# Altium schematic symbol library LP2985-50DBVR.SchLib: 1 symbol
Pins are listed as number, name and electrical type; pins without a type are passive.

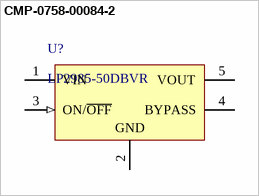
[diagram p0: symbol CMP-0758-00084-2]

## CMP-0758-00084-2
designator U?, comment LP2985-50DBVR
Single Output Low Noise LDO, 150 mA, Fixed 5 V Output, 1.5% Tolerance, 2.2 to 16 V Input, Low IQ, 5-Pin SOT-23 (DBV), -40 to 125 degC, Green (RoHS & no Sb/Br), Tape and Reel; Manufacturer: Texas Instruments; Accuracy (%): 1.5; Iout (Max) (A): 0.15; Fixed Output Options (V): 5; Vdo (Typ) (mV): 280; Output Options: Fixed Output; Iq (Typ) (mA): 0.85
footprint DBV0005A_M (SOT23, 5-Leads, Body 3.05x1.75mm, Pitch 0.95mm, IPC Low Density)
footprint DBV0005A_L (SOT23, 5-Leads, Body 3.05x1.75mm, Pitch 0.95mm, IPC High Density)
footprint DBV0005A_N (SOT23, 5-Leads, Body 3.05x1.75mm, Pitch 0.95mm, IPC Medium Density)
pins: 1 VIN (power), 2 GND (power), 3 ON/~{OFF} (in), 4 BYPASS, 5 VOUT (power)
